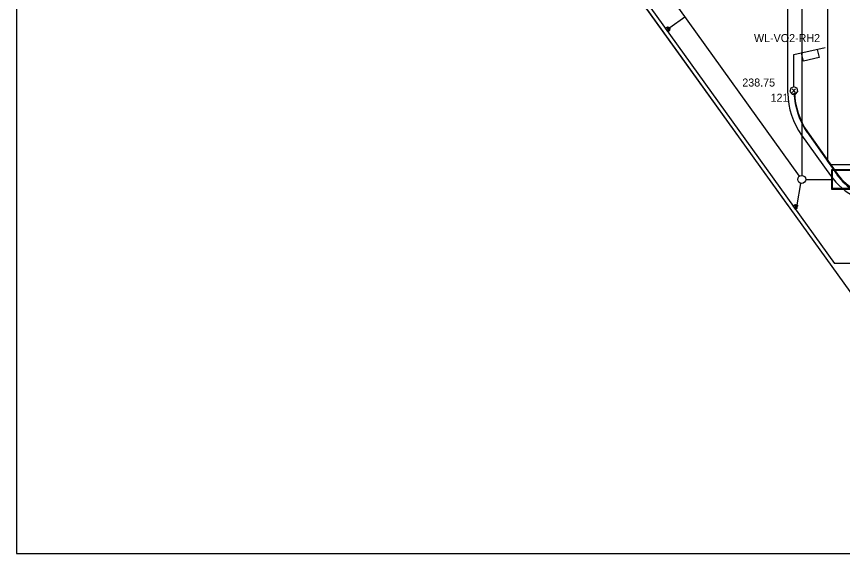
# Model space of a CAD drawing. Extents: x -264222 to -263592, y -1242345 to -1242048.
# Drawn here: x -264221.9 to -264118.8, y -1242344.9 to -1242277.9 of the extents above; entities that cross this region are included whole.
import ezdxf

# ---------------------------------------------------------------- set-up
doc = ezdxf.new("R2010")
doc.units = 0
for name, color, linetype in [('BOD_CISLO', 7, 'Continuous'), ('BOD_SYMBOL', 7, 'Continuous'), ('BOD_VYSKA', 7, 'Continuous'), ('KFA_2D_SITUACIA_DSP', 7, 'Continuous'), ('KFA_SO_62-1_VO_LAMPY_MERANE', 7, 'Continuous'), ('KFA_SO_62-1_VO_POPIS_LAMP_PROJEKT', 7, 'Continuous'), ('KFA_SO_62-1_VO_TRASA_KABLOV_PROJEKT', 7, 'Continuous'), ('RAM_NA_TLAC_1-500', 7, 'Continuous')]:
    doc.layers.add(name, color=color, linetype=linetype)

msp = doc.modelspace()

# ---------------------------------------------------------------- linework, layer by layer
at = {"layer": 'BOD_SYMBOL'}
for p, q in [((-264125.05, -1242287.39), (-264124.61, -1242286.94)), ((-264124.61, -1242287.39), (-264125.05, -1242286.94))]:
    msp.add_line(p, q, dxfattribs=at)
at = {"layer": 'KFA_2D_SITUACIA_DSP'}
for p, q in [((-264204.69, -1242191.48), (-264115.87, -1242314.98)), ((-264204.08, -1242191.48), (-264119.75, -1242308.73)), ((-264123.85, -1242237.98), (-264123.85, -1242297.74)), ((-264152.76, -1242258.05), (-264124.15, -1242297.83)), ((-264152.76, -1242258.05), (-264124.15, -1242297.83)), ((-264125.57, -1242287.47), (-264125.57, -1242270.98)), ((-264140.32, -1242279.29), (-264138.45, -1242277.94)), ((-264140.87, -1242279.37), (-264140.63, -1242279.2)), ((-264140.63, -1242279.2), (-264140.34, -1242279.61)), ((-264140.63, -1242279.2), (-264140.58, -1242279.78)), ((-264140.63, -1242279.2), (-264140.58, -1242279.78)), ((-264140.34, -1242279.61), (-264140.63, -1242279.2)), ((-264140.58, -1242279.78), (-264140.87, -1242279.37)), ((-264140.34, -1242279.61), (-264140.58, -1242279.78)), ((-264140.58, -1242279.78), (-264140.34, -1242279.61)), ((-264123.87, -1242292.72), (-264120.27, -1242297.74)), ((-264120.57, -1242296.04), (-264120.28, -1242296.43)), ((-264120.15, -1242297.04), (-264120.15, -1242299.44)), ((-264115.25, -1242297.04), (-264120.15, -1242297.04)), ((-264115.35, -1242297.14), (-264120.05, -1242297.14)), ((-264120.05, -1242297.14), (-264120.05, -1242299.34)), ((-264124.44, -1242301.41), (-264123.95, -1242298.73)), ((-264123.35, -1242298.24), (-264120.15, -1242298.24)), ((-264120.15, -1242299.44), (-264115.25, -1242299.44)), ((-264120.05, -1242299.34), (-264115.35, -1242299.34)), ((-264124.92, -1242301.54), (-264124.69, -1242301.37)), ((-264124.63, -1242301.94), (-264124.92, -1242301.54)), ((-264124.69, -1242301.37), (-264124.4, -1242301.77)), ((-264124.69, -1242301.37), (-264124.63, -1242301.94)), ((-264124.69, -1242301.37), (-264124.63, -1242301.94)), ((-264124.4, -1242301.77), (-264124.69, -1242301.37)), ((-264124.4, -1242301.77), (-264124.63, -1242301.94)), ((-264124.63, -1242301.94), (-264124.4, -1242301.77)), ((-264050.53, -1242308.73), (-264119.75, -1242308.73))]:
    msp.add_line(p, q, dxfattribs=at)
for points in [[(-264204.69, -1242191.48), (-264137.78, -1242284.52), (-264125.58, -1242301.48)], [(-264120.57, -1242296.04), (-264120.57, -1242271.19), (-264120.57, -1242271.19)], [(-263965.14, -1242296.43), (-264120.02, -1242296.43), (-264120.28, -1242296.43)]]:
    msp.add_lwpolyline(points, dxfattribs=at)
for centre, radius in [((-264140.4, -1242279.35), 0.1), ((-264123.85, -1242298.24), 0.5), ((-264124.46, -1242301.51), 0.1)]:
    msp.add_circle(centre, radius, dxfattribs=at)
for centre, start, end in [((-264116.57, -1242287.47), 180, 215.724), ((-264112.96, -1242292.48), 215.724, 270)]:
    msp.add_arc(centre, 9, start, end, dxfattribs=at)
at = {"layer": 'KFA_SO_62-1_VO_LAMPY_MERANE'}
for p, q in [((-264124.88, -1242287.16), (-264124.78, -1242287.16)), ((-264124.83, -1242287.16), (-264124.83, -1242287.16))]:
    msp.add_line(p, q, dxfattribs=at)
for points in [[(-264124.83, -1242286.66), (-264125.23, -1242286.86), (-264125.33, -1242287.26), (-264125.03, -1242287.61), (-264124.63, -1242287.61), (-264124.33, -1242287.26), (-264124.43, -1242286.86), (-264124.83, -1242286.66), (-264124.83, -1242282.66), (-264120.93, -1242281.76)], [(-264121.93, -1242282.01), (-264121.68, -1242283.01), (-264123.63, -1242283.46), (-264123.88, -1242282.46)]]:
    msp.add_lwpolyline(points, dxfattribs=at)
at = {"layer": 'KFA_SO_62-1_VO_TRASA_KABLOV_PROJEKT'}
for p, q in [((-264123.19, -1242292.35), (-264119.44, -1242297.65)), ((-264123.14, -1242292.3), (-264119.39, -1242297.6))]:
    msp.add_line(p, q, dxfattribs=at)
for centre, radius, start, end in [((-264115.07, -1242286.95), 9.76, 183.0543, 213.6093), ((-264115.02, -1242286.9), 9.76, 183.0543, 213.6093), ((-264113.25, -1242293.18), 7.64, 215.7871, 261.1375), ((-264113.76, -1242293.36), 7.05, 216.9801, 266.8749)]:
    msp.add_arc(centre, radius, start, end, dxfattribs=at)
at = {"layer": 'RAM_NA_TLAC_1-500'}
msp.add_lwpolyline([(-264221.9, -1242344.94), (-263591.9, -1242344.94), (-263591.9, -1242047.94), (-264221.9, -1242047.94)], close=True, dxfattribs=at)

# ---------------------------------------------------------------- texts
at = {"layer": 'BOD_CISLO'}
msp.add_text('121', height=1, dxfattribs=at).set_placement((-264127.74, -1242288.54))
at = {"layer": 'BOD_VYSKA'}
msp.add_text('238.75', height=1, dxfattribs=at).set_placement((-264131.27, -1242286.64))
at = {"layer": 'KFA_SO_62-1_VO_POPIS_LAMP_PROJEKT'}
msp.add_text('WL-VO2-RH2', height=1, dxfattribs=at).set_placement((-264129.81, -1242281.09))

doc.saveas('drawing.dxf')
